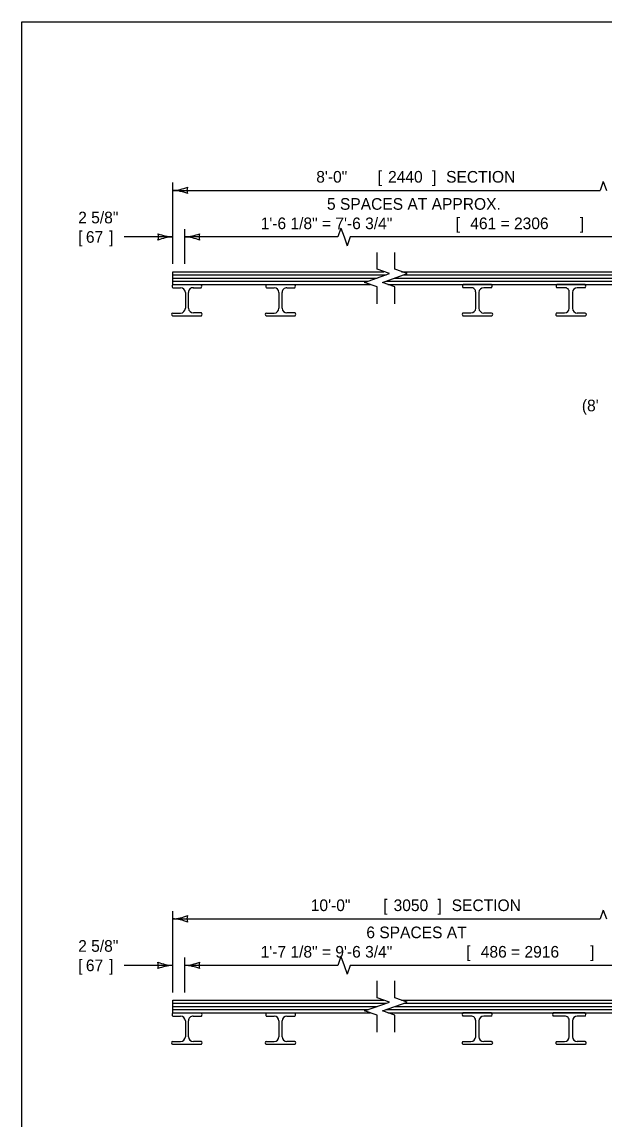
# Model space of a CAD drawing. Extents: x 49991.4 to 50021, y 49987.6 to 50011.4.
# Drawn here: x 49999.38 to 50002.38, y 49993.35 to 49999 of the extents above; entities that cross this region are included whole.
import ezdxf

# ---------------------------------------------------------------- set-up
doc = ezdxf.new("R2010")
doc.units = 0
for name, color, linetype in [('Level 1', 7, 'Continuous'), ('Level 2', 7, 'Continuous'), ('Level 3', 7, 'Continuous'), ('Level 6', 7, 'Continuous')]:
    doc.layers.add(name, color=color, linetype=linetype)

msp = doc.modelspace()

# ---------------------------------------------------------------- linework, layer by layer
at = {"layer": 'Level 1'}
for p, q in [((50000.1608, 49997.712), (50001.2499, 49997.7121)), ((50000.1608, 49997.6465), (50000.1608, 49997.712)), ((50001.3411, 49997.7121), (50004.2726, 49997.7121)), ((50000.1608, 49997.6957), (50001.2606, 49997.6957)), ((50000.1608, 49997.6793), (50001.2144, 49997.6793)), ((50000.1608, 49997.663), (50001.1684, 49997.663)), ((50000.1608, 49997.6465), (50001.1789, 49997.6465)), ((50000.1608, 49997.6459), (50000.308, 49997.6459)), ((50000.6434, 49997.6459), (50000.7906, 49997.6459)), ((50001.2596, 49997.663), (50004.1911, 49997.663)), ((50001.2701, 49997.6465), (50004.2016, 49997.6465)), ((50001.3056, 49997.6793), (50004.2371, 49997.6793)), ((50001.3518, 49997.6957), (50004.2833, 49997.6957)), ((50001.8048, 49997.6458), (50001.6577, 49997.6458)), ((50002.2874, 49997.6458), (50002.1403, 49997.6458)), ((50000.1609, 49997.6295), (50000.2015, 49997.6296)), ((50000.226, 49997.6051), (50000.226, 49997.5235)), ((50000.2428, 49997.5237), (50000.2428, 49997.6052)), ((50000.2671, 49997.6297), (50000.308, 49997.6295)), ((50000.6435, 49997.6295), (50000.6841, 49997.6296)), ((50000.7086, 49997.6051), (50000.7086, 49997.5235)), ((50000.7254, 49997.5237), (50000.7254, 49997.6052)), ((50000.7497, 49997.6297), (50000.7906, 49997.6295)), ((50001.6985, 49997.6297), (50001.6577, 49997.6295)), ((50001.7229, 49997.5237), (50001.7229, 49997.6052)), ((50001.7396, 49997.6051), (50001.7396, 49997.5235)), ((50001.8048, 49997.6295), (50001.7642, 49997.6295)), ((50002.1811, 49997.6297), (50002.1403, 49997.6295)), ((50002.2055, 49997.5237), (50002.2055, 49997.6052)), ((50002.2222, 49997.6051), (50002.2222, 49997.5235)), ((50002.2874, 49997.6295), (50002.2468, 49997.6295)), ((50000.1603, 49997.4851), (50000.3094, 49997.4851)), ((50000.1612, 49997.4989), (50000.2016, 49997.4989)), ((50000.3087, 49997.4993), (50000.2674, 49997.4993)), ((50000.6429, 49997.4851), (50000.792, 49997.4851)), ((50000.6438, 49997.4989), (50000.6842, 49997.4989)), ((50000.7913, 49997.4993), (50000.75, 49997.4993)), ((50001.6562, 49997.4851), (50001.8055, 49997.4851)), ((50001.6569, 49997.4993), (50001.6983, 49997.4993)), ((50001.8045, 49997.4988), (50001.7641, 49997.4989)), ((50002.1388, 49997.4851), (50002.2881, 49997.4851)), ((50002.1395, 49997.4993), (50002.1809, 49997.4993)), ((50002.2871, 49997.4988), (50002.2467, 49997.4989)), ((50000.1607, 49993.958), (50001.2498, 49993.9581)), ((50000.1607, 49993.8925), (50000.1607, 49993.958)), ((50000.1607, 49993.9417), (50001.2605, 49993.9417)), ((50000.1607, 49993.9253), (50001.2143, 49993.9253)), ((50001.3055, 49993.9253), (50004.237, 49993.9253)), ((50001.341, 49993.9581), (50004.2725, 49993.9581)), ((50001.3517, 49993.9417), (50004.2832, 49993.9417)), ((50000.1607, 49993.909), (50001.1683, 49993.909)), ((50000.1607, 49993.8925), (50001.1788, 49993.8925)), ((50000.1607, 49993.8919), (50000.3086, 49993.8921)), ((50000.1608, 49993.8755), (50000.2014, 49993.8756)), ((50000.267, 49993.8757), (50000.3086, 49993.8758)), ((50000.6433, 49993.8919), (50000.7912, 49993.8921)), ((50000.6434, 49993.8755), (50000.684, 49993.8756)), ((50000.7496, 49993.8757), (50000.7912, 49993.8758)), ((50001.2595, 49993.909), (50004.191, 49993.909)), ((50001.27, 49993.8925), (50004.2015, 49993.8925)), ((50001.8047, 49993.8918), (50001.6568, 49993.8921)), ((50001.6984, 49993.8757), (50001.6568, 49993.8757)), ((50001.8047, 49993.8755), (50001.7641, 49993.8755)), ((50002.2873, 49993.8918), (50002.1223, 49993.8921)), ((50002.181, 49993.8757), (50002.1223, 49993.8757)), ((50002.2873, 49993.8755), (50002.2467, 49993.8755)), ((50000.2259, 49993.8511), (50000.2259, 49993.7695)), ((50000.2427, 49993.7697), (50000.2427, 49993.8512)), ((50000.7085, 49993.8511), (50000.7085, 49993.7695)), ((50000.7253, 49993.7697), (50000.7253, 49993.8512)), ((50001.7228, 49993.7697), (50001.7228, 49993.8512)), ((50001.7395, 49993.8511), (50001.7395, 49993.7695)), ((50002.2054, 49993.7697), (50002.2054, 49993.8512)), ((50002.2221, 49993.8511), (50002.2221, 49993.7695)), ((50000.1611, 49993.7449), (50000.2015, 49993.7449)), ((50000.3086, 49993.7453), (50000.2673, 49993.7453)), ((50000.6437, 49993.7449), (50000.6841, 49993.7449)), ((50000.7912, 49993.7453), (50000.7499, 49993.7453)), ((50001.6568, 49993.7453), (50001.6982, 49993.7453)), ((50001.8044, 49993.7448), (50001.764, 49993.7449)), ((50002.1394, 49993.7453), (50002.1808, 49993.7453)), ((50002.287, 49993.7448), (50002.2466, 49993.7449)), ((50000.1602, 49993.7311), (50000.3093, 49993.7311)), ((50000.6428, 49993.7311), (50000.7919, 49993.7311)), ((50001.6561, 49993.7311), (50001.8054, 49993.7311)), ((50002.1387, 49993.7311), (50002.288, 49993.7311))]:
    msp.add_line(p, q, dxfattribs=at)
msp.add_lwpolyline([(49999.3835, 49998.9992), (50016.7501, 49998.9992), (50016.7501, 49987.7988), (49999.3835, 49987.7988)], close=True, dxfattribs=at)
for centre, radius, start, end in [((50000.2015, 49997.6051), 0.0245, 0.1309, 90.1308), ((50000.2652, 49997.6073), 0.0225, 85.0314, 185.3256), ((50000.6841, 49997.6051), 0.0245, 0.1309, 90.1308), ((50000.7489, 49997.6062), 0.0235, 88.0071, 182.3499), ((50001.6998, 49997.6066), 0.0231, 356.4913, 93.1517), ((50001.7641, 49997.605), 0.0245, 89.8692, 179.8692), ((50002.1827, 49997.6069), 0.0228, 355.5982, 94.0447), ((50002.2467, 49997.605), 0.0245, 89.8692, 179.8692), ((50000.2015, 49997.5234), 0.0245, 270.1309, 0.1308), ((50000.2673, 49997.5238), 0.0245, 180.1309, 270.1309), ((50000.6841, 49997.5234), 0.0245, 270.1309, 0.1308), ((50000.7499, 49997.5238), 0.0245, 180.1309, 270.1309), ((50001.6984, 49997.5238), 0.0245, 269.8691, 359.8691), ((50001.7641, 49997.5234), 0.0245, 179.8691, 269.8691), ((50002.181, 49997.5238), 0.0245, 269.8691, 359.8691), ((50002.2467, 49997.5234), 0.0245, 179.8691, 269.8691), ((50000.2014, 49993.8511), 0.0245, 0.1309, 90.1308), ((50000.2647, 49993.8537), 0.0221, 83.8969, 186.4601), ((50000.684, 49993.8511), 0.0245, 0.1309, 90.1308), ((50000.7497, 49993.8513), 0.0245, 90.2573, 180.0997), ((50001.6999, 49993.8528), 0.0229, 356.005, 93.638), ((50001.764, 49993.851), 0.0245, 89.8692, 179.8692), ((50002.1823, 49993.8526), 0.0231, 356.4904, 93.1526), ((50002.2466, 49993.851), 0.0245, 89.8692, 179.8692), ((50000.2014, 49993.7694), 0.0245, 270.1309, 0.1308), ((50000.2672, 49993.7698), 0.0245, 180.1309, 270.1309), ((50000.684, 49993.7694), 0.0245, 270.1309, 0.1308), ((50000.7498, 49993.7698), 0.0245, 180.1309, 270.1309), ((50001.6983, 49993.7698), 0.0245, 269.8691, 359.8691), ((50001.764, 49993.7694), 0.0245, 179.8691, 269.8691), ((50002.1809, 49993.7698), 0.0245, 269.8691, 359.8691), ((50002.2466, 49993.7694), 0.0245, 179.8691, 269.8691)]:
    msp.add_arc(centre, radius, start, end, dxfattribs=at)
for centre, major_axis, ratio, start_param, end_param in [((50000.1609, 49997.6377), (-0.00002, 0.00817), 0.356754, 0, 3.141593), ((50000.308, 49997.6377), (0.00002, 0.00817), 0.356754, 3.141593, 6.283185), ((50000.6435, 49997.6377), (-0.00002, 0.00817), 0.356754, 0, 3.141593), ((50000.7906, 49997.6377), (0.00002, 0.00817), 0.356754, 3.141593, 6.283185), ((50001.6577, 49997.6377), (-0.00002, 0.00817), 0.356754, 0, 3.141593), ((50001.8048, 49997.6377), (0.00002, 0.00817), 0.356754, 3.141593, 6.283185), ((50002.1403, 49997.6377), (-0.00002, 0.00817), 0.356754, 0, 3.141593), ((50002.2874, 49997.6377), (0.00002, 0.00817), 0.356754, 3.141593, 6.283185), ((50000.1614, 49997.4919), (-0.00025, 0.00695), 0.928868, 0, 2.919512), ((50000.3087, 49997.4921), (-0.00003, -0.00717), 0.534325, 0.187696, 3.141593), ((50000.644, 49997.4919), (-0.00025, 0.00695), 0.928868, 0, 2.919512), ((50000.7913, 49997.4921), (-0.00003, -0.00717), 0.534325, 0.187696, 3.141593), ((50001.657, 49997.4921), (0.00003, -0.00717), 0.534325, 3.141593, 6.076715), ((50001.8042, 49997.4919), (0.00025, 0.00695), 0.928868, 3.382741, 6.283185), ((50002.1396, 49997.4921), (0.00003, -0.00717), 0.534325, 3.141593, 6.076713), ((50002.2868, 49997.4919), (0.00025, 0.00695), 0.928868, 3.382741, 6.283185), ((50000.1608, 49993.8837), (-0.00002, 0.00817), 0.356754, 0, 3.141593), ((50000.3086, 49993.8839), (0.00002, -0.00817), 0.392805, 0, 3.141593), ((50000.6434, 49993.8837), (-0.00002, 0.00817), 0.356754, 0, 3.141593), ((50000.7912, 49993.8839), (0.00002, -0.00817), 0.392805, 0, 3.141593), ((50001.6569, 49993.8839), (-0.00002, -0.00817), 0.392805, 3.141593, 6.283185), ((50001.8047, 49993.8837), (0.00002, 0.00817), 0.356754, 3.141593, 6.283185), ((50002.1223, 49993.8839), (-0.00002, -0.00817), 0.392805, 3.141593, 6.283185), ((50002.2873, 49993.8837), (0.00002, 0.00817), 0.356754, 3.141593, 6.283185), ((50000.1613, 49993.7379), (-0.00025, 0.00695), 0.928868, 0, 2.919512), ((50000.3086, 49993.7381), (-0.00003, -0.00717), 0.534325, 0.187696, 3.141593), ((50000.6439, 49993.7379), (-0.00025, 0.00695), 0.928868, 0, 2.919512), ((50000.7912, 49993.7381), (-0.00003, -0.00717), 0.534325, 0.187696, 3.141593), ((50001.6569, 49993.7381), (0.00003, -0.00717), 0.534325, 3.141593, 6.076715), ((50001.8041, 49993.7379), (0.00025, 0.00695), 0.928868, 3.382741, 6.283185), ((50002.1395, 49993.7381), (0.00003, -0.00717), 0.534325, 3.141593, 6.076713), ((50002.2867, 49993.7379), (0.00025, 0.00695), 0.928868, 3.382741, 6.283185)]:
    msp.add_ellipse(centre, major_axis=major_axis, ratio=ratio, start_param=start_param, end_param=end_param, dxfattribs=at)
at = {"layer": 'Level 3'}
for p, q in [((50000.1608, 49997.752), (50000.1608, 49998.1712)), ((50002.3802, 49998.1765), (50002.364, 49998.1309)), ((50002.3802, 49998.1765), (50002.3964, 49998.1309)), ((50000.1608, 49998.1312), (50001.9664, 49998.1309)), ((50001.9664, 49998.1309), (50002.364, 49998.1309)), ((50000.2232, 49997.752), (50000.2232, 49997.9312)), ((50001.0278, 49997.937), (50001.0116, 49997.8912)), ((50001.0278, 49997.937), (50001.044, 49997.8912)), ((50000.1608, 49997.8912), (49999.9106, 49997.8912)), ((50001.0116, 49997.8912), (50000.2232, 49997.8912)), ((50001.044, 49997.8912), (50001.0602, 49997.8456)), ((50001.0764, 49997.8912), (50001.0602, 49997.8456)), ((50002.6886, 49997.8912), (50001.0764, 49997.8912)), ((50002.3801, 49994.4225), (50002.3639, 49994.3769)), ((50002.3801, 49994.4225), (50002.3963, 49994.3769)), ((50000.1607, 49993.998), (50000.1607, 49994.4172)), ((50000.1607, 49994.3772), (50001.9663, 49994.3769)), ((50001.9663, 49994.3769), (50002.3639, 49994.3769)), ((50000.2231, 49993.998), (50000.2231, 49994.1772)), ((50001.0277, 49994.183), (50001.0115, 49994.1372)), ((50001.0277, 49994.183), (50001.0439, 49994.1372)), ((50000.1607, 49994.1372), (49999.9105, 49994.1372)), ((50001.0115, 49994.1372), (50000.2231, 49994.1372)), ((50001.0439, 49994.1372), (50001.0601, 49994.0916)), ((50001.0763, 49994.1372), (50001.0601, 49994.0916)), ((50002.6885, 49994.1372), (50001.0763, 49994.1372))]:
    msp.add_line(p, q, dxfattribs=at)
for centre, radius, start, end in [((50000.1493, 49998.3639), 0.233, 272.8273, 292.0772), ((50000.1517, 49997.9091), 0.2223, 67.456, 87.6395), ((50000.2891, 49998.1312), 0.0548, 162.1388, 197.8612), ((50000.17, 49998.1133), 0.2223, 247.456, 267.6395), ((50000.0326, 49997.8912), 0.0548, 342.1388, 17.8612), ((50000.1723, 49997.6585), 0.233, 92.8273, 112.0772), ((50000.2118, 49998.1239), 0.233, 272.8273, 292.0772), ((50000.2141, 49997.6691), 0.2223, 67.456, 87.6395), ((50000.3515, 49997.8912), 0.0548, 162.1388, 197.8612), ((50000.1492, 49994.6099), 0.233, 272.8273, 292.0772), ((50000.1516, 49994.1551), 0.2223, 67.456, 87.6395), ((50000.289, 49994.3772), 0.0548, 162.1388, 197.8612), ((50000.1699, 49994.3593), 0.2223, 247.456, 267.6395), ((50000.0325, 49994.1372), 0.0548, 342.1388, 17.8612), ((50000.2117, 49994.3699), 0.233, 272.8273, 292.0772), ((50000.3514, 49994.1372), 0.0548, 162.1388, 197.8612), ((50000.1722, 49993.9045), 0.233, 92.8273, 112.0772), ((50000.214, 49993.9151), 0.2223, 67.456, 87.6395)]:
    msp.add_arc(centre, radius, start, end, dxfattribs=at)
at = {"layer": 'Level 6'}
for points in [[(50001.2144, 49997.5468), (50001.2144, 49997.6339), (50001.1504, 49997.6566), (50001.2784, 49997.702), (50001.2144, 49997.7247), (50001.2144, 49997.8118)], [(50001.3056, 49997.5468), (50001.3056, 49997.6339), (50001.2416, 49997.6566), (50001.3696, 49997.702), (50001.3056, 49997.7247), (50001.3056, 49997.8118)], [(50001.2143, 49993.7928), (50001.2143, 49993.8799), (50001.1503, 49993.9026), (50001.2783, 49993.948), (50001.2143, 49993.9707), (50001.2143, 49994.0578)], [(50001.3055, 49993.7928), (50001.3055, 49993.8799), (50001.2415, 49993.9026), (50001.3695, 49993.948), (50001.3055, 49993.9707), (50001.3055, 49994.0578)]]:
    msp.add_lwpolyline(points, dxfattribs=at)

# ---------------------------------------------------------------- texts
at = {"layer": 'Level 2'}
for s, p in [('8\'-0" ', (50000.9008, 49998.1711)), ('[', (50001.2176, 49998.1711)), ('2440', (50001.2709, 49998.1711)), (']', (50001.4973, 49998.1711)), (' SECTION', (50001.5481, 49998.1711)), ('5 SPACES AT APPROX.', (50000.9561, 49998.0312)), ('2 5/8"', (49999.6736, 49997.9612)), ('1\'-6 1/8" = 7\'-6 3/4" ', (50000.6143, 49997.9312)), ('[', (50001.6196, 49997.9312)), ('461 = 2306', (50001.6949, 49997.9312)), (']', (50002.2593, 49997.9312)), ('[', (49999.6736, 49997.8612)), ('67', (49999.7133, 49997.8612)), (']', (49999.8333, 49997.8612)), ("(8' ", (50002.2701, 49996.9926)), ('10\'-0" ', (50000.8726, 49994.417)), ('[', (50001.2463, 49994.417)), ('3050', (50001.2995, 49994.417)), (']', (50001.5259, 49994.417)), (' SECTION', (50001.5768, 49994.417)), ('6 SPACES AT', (50001.159, 49994.2772)), ('2 5/8"', (49999.6735, 49994.2072)), ('1\'-7 1/8" = 9\'-6 3/4" ', (50000.6141, 49994.1772)), ('[', (50001.6737, 49994.1772)), ('486 = 2916', (50001.749, 49994.1772)), (']', (50002.3134, 49994.1772)), ('[', (49999.6735, 49994.1072)), ('67', (49999.7132, 49994.1072)), (']', (49999.8332, 49994.1072))]:
    msp.add_text(s, height=0.06, dxfattribs=at).set_placement(p)

doc.saveas('drawing.dxf')
